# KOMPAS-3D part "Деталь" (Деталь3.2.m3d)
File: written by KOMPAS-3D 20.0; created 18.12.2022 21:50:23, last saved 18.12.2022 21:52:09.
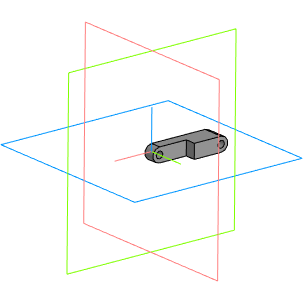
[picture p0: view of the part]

Document properties: Полное имя файла: C:\Users\Семья\Desktop\ДЕТАЛИ ДЛЯ СБОРЩИКА БОРЩЕВИКА\Деталь3.2.m3d

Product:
- Part/product: Деталь
    Масса: 0.00248465
  - Body: Тело 1
      Масса: 0.00165643

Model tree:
1. Эскиз:1
2. Элемент выдавливания:1
     Расстояние 1 = 3
3. Эскиз:2  (with: Элемент выдавливания:1)
4. Элемент выдавливания:3
     Расстояние 1 = 3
